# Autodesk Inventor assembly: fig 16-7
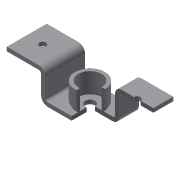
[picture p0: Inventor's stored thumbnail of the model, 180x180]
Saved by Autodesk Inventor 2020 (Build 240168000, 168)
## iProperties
Created: 2005-03
Part Number: fig 16-7
Document SubType Name: Weldment
Designer: CADCIM
Manufacturer: Standard
Standards Organization: Custom
Author: CADCIM
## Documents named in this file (3)
- D:\Autodesk Inventor_2020\Resources\Resources\Inventor_2020_Part\Inventor_2020_Part\c16_Inv_2020_prt\fig 16-7\fig 16-7.iam
- D:\Autodesk Inventor_2020\Resources\Resources\Inventor_2020_Part\Inventor_2020_Part\c16_Inv_2020_prt\fig 16-7\Bracket.ipt
- D:\Autodesk Inventor_2020\Resources\Resources\Inventor_2020_Part\Inventor_2020_Part\c16_Inv_2020_prt\fig 16-7\cylinder.ipt
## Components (2 placed, 2 different names)
1. Bracket:1 — Insert:1
2. cylinder:1 — Insert:1
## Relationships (1: Insert 1)
- Insert:1: Bracket:1 ↔ cylinder:1
